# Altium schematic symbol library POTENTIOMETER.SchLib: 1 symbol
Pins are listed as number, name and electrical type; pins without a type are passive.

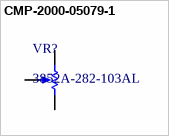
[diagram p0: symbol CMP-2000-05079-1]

## CMP-2000-05079-1
designator VR?, comment 3852A-282-103AL
Diameter Panel Control, 10 KOhm, +/- 10%, 2 W, -1 to 125 degC, 3-Pin THD, RoHS, Bulk; Manufacturer: Bourns; Temperature Coefficient: ±150ppm/degC; Number of Gangs: 1; Other Names: 3852A282103AL; Actuator Length: 0.875"(22.23mm); Resistive Material: Cermet; PCN Design/Specification: PBTResinJun/2011; Rotation: 280deg; PCN Other: MultipleChanges01/Dec/2012; Catalog Drawings: 3852SeriesSide1 / 3852SeriesSide2; Online Catalog: 3852and3856Series; Associated Product: 36-8560-ND / -KNOBINSTRUMW/DIALRND.9"DIA / 36-8555-ND / -KNOBINSTRUMSKIRTEDRND.7"DIA / 36-8556-ND / -KNOBINSTRUMSKIRTEDRND.9"DIA / 36-8565-ND / -KNOBINSTRUMDBLBARRND.7"DIA / 36-8566-ND / -KNOBINSTRUMDBLBARRND.9"DIA / 36-8568-ND / -KNOBINSTRUMSGLBARRND.7"DIA / 36-8569-ND / -KNOBINSTRUMSGLBARRND.9"DIA / 36-8559-ND / -KNOBINSTRUMW/DIALRND.7"DIA / 226-1006-ND / -KNOBBLKGLOSS.75"DIA.250"SHAFT / 226-1007-ND / -KNOBBLKGLOSS.925"DIA.250"SHAFT / 226-1011-ND / -KNOBBLKGLOS; Actuator Diameter: 0.250"(6.35mm); Built in Switch: None; Resistance (Ohms): 10k; Power (Watts): 2W; Actuator Type: Slotted
footprint BOUR-3852A-282-103AL-3_V (TH, 3-Leads, Body 19.81x19.05mm, Pitch 6.35mm)
pins: 1 CCW, 2 S, 3 CW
